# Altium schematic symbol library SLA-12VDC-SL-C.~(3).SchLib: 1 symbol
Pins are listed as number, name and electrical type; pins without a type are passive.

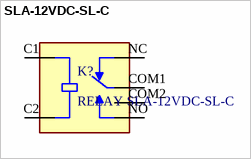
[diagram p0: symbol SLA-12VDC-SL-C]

## SLA-12VDC-SL-C
designator K?, comment RELAY SLA-12VDC-SL-C
SLA-12VDC-SL-C Ningbo Songle Relay-250V@AC 12V 30A 1 Form C: 1C (SPDT-CO) Plugin,27.6x32mm Power Relays ROHS
footprint RELAY_SLA-12VDC-SL-C
pins: C1 COIL1, C2 COIL2, COM1 COM, COM2 COM, NC, NO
